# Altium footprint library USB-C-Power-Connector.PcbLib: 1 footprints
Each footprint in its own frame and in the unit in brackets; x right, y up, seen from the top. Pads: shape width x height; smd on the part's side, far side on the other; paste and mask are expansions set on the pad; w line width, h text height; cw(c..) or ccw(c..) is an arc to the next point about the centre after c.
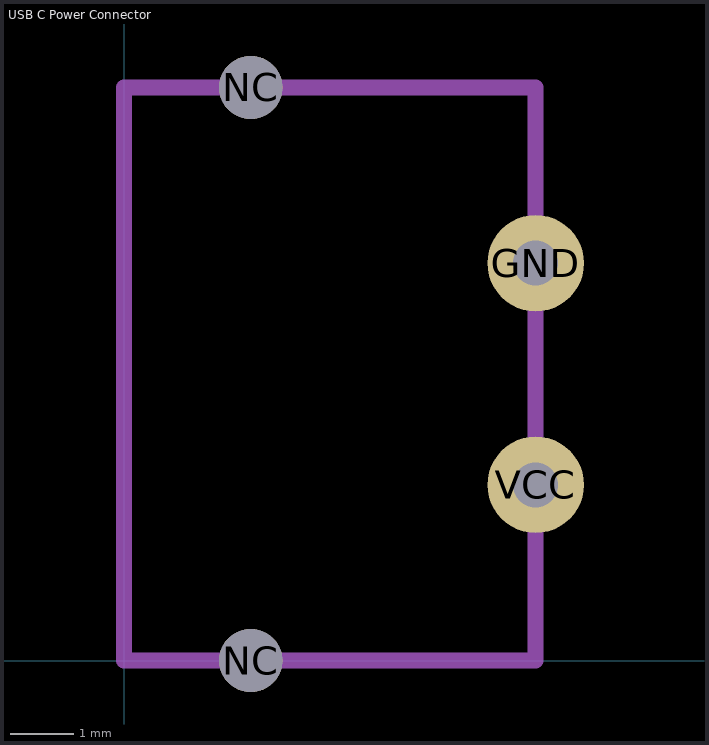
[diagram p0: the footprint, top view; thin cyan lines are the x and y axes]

## USB C Power Connector [mm]
pads (4):
  round 1.524 smd: GND(6.5,6.275) VCC(6.5,2.775)
  round 1 hole 1 mask+0: NC(2,0)
  round 1 hole 1 paste-2539.97 mask+0: NC(2,9.05)
via 6.5,2.775 diameter 1.27 hole 0.711
via 6.5,6.275 diameter 1.27 hole 0.711
Mechanical 1:
  lines w0.254: 0,0 6.5,0 6.5,9.05 0,9.05 0,0
3D body "USB.step": height 3, standoff -2, extent 0.052,0.047 6.552,9.097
